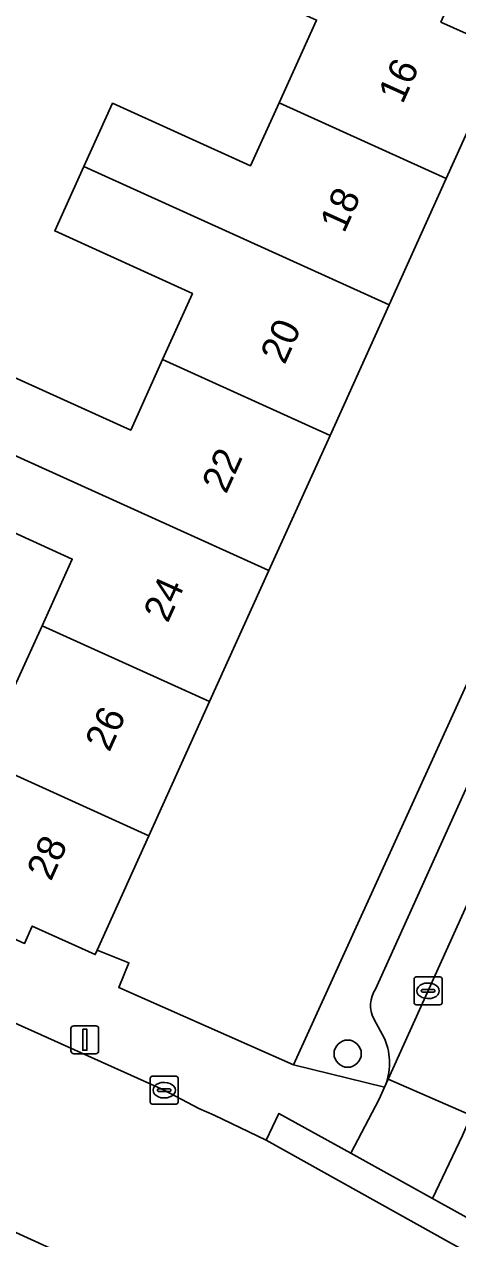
# Model space of a CAD drawing. Extents: x 161838 to 162344, y 381620 to 382160.
# Drawn here: x 162064.83 to 162080.38, y 381747.04 to 381790.62 of the extents above; entities that cross this region are included whole.
import ezdxf

# ---------------------------------------------------------------- set-up
doc = ezdxf.new("R2010")
doc.units = 0
for name, color, linetype in [('IMGEO_Boom', 7, 'Continuous'), ('IMGEO_Erf', 7, 'Continuous'), ('IMGEO_Kolk', 7, 'Continuous'), ('IMGEO_Lichtmast', 7, 'Continuous'), ('IMGEO_Pand', 7, 'Continuous'), ('IMGEO_Pand_nummerreeks', 7, 'Continuous'), ('IMGEO_Parkeervlak_open', 7, 'Continuous'), ('IMGEO_Rijbaan_lokaal_open', 7, 'Continuous'), ('IMGEO_Voetpad_open', 7, 'Continuous')]:
    doc.layers.add(name, color=color, linetype=linetype)

msp = doc.modelspace()

# ---------------------------------------------------------------- linework, layer by layer
at = {"layer": 'IMGEO_Boom'}
msp.add_circle((162076.43, 381753.682), 0.489, dxfattribs=at)
at = {"layer": 'IMGEO_Erf'}
for points in [[(162063.703, 381778.29), (162068.645, 381776.051), (162069.789, 381778.584), (162070.858, 381780.953), (162065.92, 381783.202), (162066.965, 381785.512), (162067.993, 381787.785), (162072.946, 381785.539), (162073.969, 381787.795), (162075.316, 381790.766), (162070.431, 381792.976), (162071.424, 381795.171), (162065.308, 381798.05), (162064.526, 381796.39), (162066.838, 381795.353), (162065.298, 381791.922), (162062.882, 381793.006)], [(162064.418, 381766.726), (162065.465, 381769.039), (162066.546, 381771.429), (162061.613, 381773.671)]]:
    msp.add_lwpolyline(points, dxfattribs=at)
msp.add_lwpolyline([(162068.579, 381756.936), (162068.219, 381756.057), (162074.49, 381753.282), (162089.747, 381786.804), (162083.445, 381789.649), (162083.105, 381788.89), (162081.916, 381789.39), (162079.965, 381785.079), (162077.918, 381780.552), (162075.797, 381775.863), (162073.603, 381771.013), (162071.478, 381766.316), (162069.301, 381761.504), (162067.446, 381757.401)], close=True, dxfattribs=at)
at = {"layer": 'IMGEO_Kolk'}
for p, q in [((162078.813, 381755.511), (162078.813, 381756.363)), ((162078.888, 381756.437), (162079.74, 381756.437)), ((162079.301, 381756.217), (162079.326, 381756.217)), ((162079.814, 381756.363), (162079.814, 381755.511)), ((162079.072, 381755.931), (162079.072, 381755.943)), ((162079.51, 381755.894), (162079.112, 381755.894)), ((162079.115, 381755.98), (162079.513, 381755.98)), ((162079.324, 381755.657), (162079.299, 381755.657)), ((162079.556, 381755.943), (162079.556, 381755.931)), ((162079.74, 381755.437), (162078.888, 381755.437)), ((162069.346, 381751.946), (162069.346, 381752.798)), ((162069.421, 381752.872), (162070.273, 381752.872)), ((162069.834, 381752.652), (162069.859, 381752.652)), ((162070.347, 381752.798), (162070.347, 381751.946)), ((162069.605, 381752.366), (162069.605, 381752.378)), ((162070.043, 381752.329), (162069.645, 381752.329)), ((162069.648, 381752.415), (162070.046, 381752.415)), ((162070.089, 381752.378), (162070.089, 381752.366)), ((162070.273, 381751.872), (162069.421, 381751.872)), ((162069.857, 381752.092), (162069.832, 381752.092))]:
    msp.add_line(p, q, dxfattribs=at)
for points in [[(162078.813, 381755.511), (162078.813, 381756.363)], [(162078.888, 381756.437), (162079.74, 381756.437)], [(162079.814, 381756.363), (162079.814, 381755.511)], [(162079.74, 381755.437), (162078.888, 381755.437)], [(162069.346, 381751.946), (162069.346, 381752.798)], [(162069.421, 381752.872), (162070.273, 381752.872)], [(162070.347, 381752.798), (162070.347, 381751.946)], [(162070.273, 381751.872), (162069.421, 381751.872)]]:
    msp.add_lwpolyline(points, dxfattribs=at)
for centre, radius, start, end in [((162078.89, 381756.361), 0.0765, 91.552, 178.448), ((162078.89, 381756.361), 0.0765, 91.552, 178.448), ((162079.738, 381756.361), 0.0765, 1.552, 88.448), ((162079.738, 381756.361), 0.0765, 1.552, 88.448), ((162079.112, 381755.94), 0.0403, 85.8775, 175.7526), ((162079.109, 381755.93), 0.0366, 178.938, 274.7102), ((162079.513, 381755.937), 0.043, 264.8664, 352.4533), ((162079.517, 381755.942), 0.0386, 1.7309, 96.639), ((162078.89, 381755.513), 0.0765, 181.552, 268.448), ((162078.89, 381755.513), 0.0765, 181.552, 268.448), ((162079.738, 381755.513), 0.0765, 271.552, 358.448), ((162079.738, 381755.513), 0.0765, 271.552, 358.448), ((162069.423, 381752.796), 0.0765, 91.552, 178.448), ((162069.423, 381752.796), 0.0765, 91.552, 178.448), ((162070.271, 381752.796), 0.0765, 1.552, 88.448), ((162070.271, 381752.796), 0.0765, 1.552, 88.448), ((162069.645, 381752.375), 0.0403, 85.8775, 175.7526), ((162069.642, 381752.365), 0.0366, 178.938, 274.7102), ((162070.046, 381752.372), 0.043, 264.8664, 352.4533), ((162070.05, 381752.377), 0.0386, 1.7309, 96.639), ((162069.423, 381751.948), 0.0765, 181.552, 268.448), ((162069.423, 381751.948), 0.0765, 181.552, 268.448), ((162070.271, 381751.948), 0.0765, 271.552, 358.448), ((162070.271, 381751.948), 0.0765, 271.552, 358.448)]:
    msp.add_arc(centre, radius, start, end, dxfattribs=at)
for centre, major_axis, ratio, start_param, end_param in [((162079.3, 381755.937), (-0.387, 0.002), 0.722429, 4.712389, 7.853982), ((162079.325, 381755.937), (-0.39, 0.002), 0.717154, 1.570796, 4.712389), ((162069.833, 381752.372), (-0.387, 0.002), 0.722429, 4.712389, 7.853982), ((162069.858, 381752.372), (-0.39, 0.002), 0.717154, 1.570796, 4.712389)]:
    msp.add_ellipse(centre, major_axis=major_axis, ratio=ratio, start_param=start_param, end_param=end_param, dxfattribs=at)
at = {"layer": 'IMGEO_Lichtmast'}
for p, q in [((162066.503, 381753.781), (162066.503, 381754.581)), ((162066.503, 381754.581), (162066.503, 381753.781)), ((162066.603, 381754.681), (162067.393, 381754.681)), ((162067.393, 381754.681), (162066.603, 381754.681)), ((162067.493, 381754.581), (162067.493, 381753.781)), ((162067.493, 381753.781), (162067.493, 381754.581)), ((162067.393, 381753.681), (162066.603, 381753.681)), ((162066.603, 381753.681), (162067.393, 381753.681))]:
    msp.add_line(p, q, dxfattribs=at)
msp.add_lwpolyline([(162066.923, 381754.556), (162067.073, 381754.556), (162067.073, 381753.806), (162066.923, 381753.806), (162066.923, 381754.556)], dxfattribs=at)
for centre, start, end in [((162066.603, 381754.581), 90, 180), ((162066.603, 381754.581), 90, 180), ((162067.393, 381754.581), 0, 90), ((162067.393, 381754.581), 360, 90), ((162066.603, 381753.781), 180, 270), ((162066.603, 381753.781), 180, 270), ((162067.393, 381753.781), 270, 0), ((162067.393, 381753.781), 270, 0)]:
    msp.add_arc(centre, 0.1, start, end, dxfattribs=at)
at = {"layer": 'IMGEO_Pand'}
for points in [[(162073.969, 381787.795), (162079.965, 381785.079), (162081.916, 381789.39), (162082.043, 381789.672), (162079.775, 381790.698), (162080.088, 381791.39), (162071.424, 381795.171), (162070.431, 381792.976), (162075.316, 381790.766)], [(162077.918, 381780.552), (162079.965, 381785.079), (162073.969, 381787.795), (162072.946, 381785.539), (162067.993, 381787.785), (162066.965, 381785.512)], [(162075.797, 381775.863), (162077.918, 381780.552), (162066.965, 381785.512), (162065.92, 381783.202), (162070.858, 381780.953), (162069.789, 381778.584)], [(162075.797, 381775.863), (162069.789, 381778.584), (162068.645, 381776.051), (162063.703, 381778.29), (162062.654, 381775.972), (162073.603, 381771.013)], [(162065.465, 381769.039), (162071.478, 381766.316), (162073.603, 381771.013), (162062.654, 381775.972), (162061.613, 381773.671), (162066.546, 381771.429)], [(162069.301, 381761.504), (162071.478, 381766.316), (162065.465, 381769.039), (162064.418, 381766.726), (162059.499, 381768.952), (162058.368, 381766.456)], [(162069.301, 381761.504), (162058.368, 381766.456), (162057.435, 381764.397), (162062.381, 381762.156), (162061.101, 381759.332), (162064.835, 381757.639), (162065.115, 381758.257), (162067.371, 381757.236), (162067.446, 381757.401)]]:
    msp.add_lwpolyline(points, close=True, dxfattribs=at)
at = {"layer": 'IMGEO_Parkeervlak_open'}
for points in [[(162077.753, 381752.48), (162077.885, 381752.773), (162091.2, 381782.254)], [(162088.368, 381780.23), (162077.427, 381756)], [(162077.369, 381754.933), (162077.765, 381754.199)]]:
    msp.add_lwpolyline(points, dxfattribs=at)
for centre, radius, start, end in [((162078.307, 381755.417), 1.056, 146.4825, 207.2947), ((162075.671, 381753.354), 2.258, 337.2236, 21.9765)]:
    msp.add_arc(centre, radius, start, end, dxfattribs=at)
at = {"layer": 'IMGEO_Rijbaan_lokaal_open'}
for points in [[(162094.929, 381782.528), (162095.383, 381783.532), (162092.357, 381784.815), (162091.2, 381782.254), (162077.885, 381752.773), (162080.868, 381751.463)], [(162080.79, 381751.291), (162080.868, 381751.463), (162077.885, 381752.773), (162077.753, 381752.48), (162077.557, 381752.046), (162076.538, 381750.111), (162079.471, 381748.488), (162080.545, 381750.749)]]:
    msp.add_lwpolyline(points, close=True, dxfattribs=at)
msp.add_lwpolyline([(162015.372, 381769.412), (162017.318, 381768.637), (162049.197, 381754.238), (162052.77, 381752.631), (162056.86, 381750.762), (162068.214, 381745.584), (162068.985, 381745.23), (162081.324, 381741.038), (162082.15, 381740.62), (162087.294, 381738.315), (162101.774, 381731.795), (162101.956, 381731.713), (162103.87, 381735.811), (162103.292, 381736.059), (162084.495, 381744.526), (162081.506, 381746.115), (162073.51, 381750.574), (162071.642, 381751.481), (162071.089, 381751.71), (162069.847, 381752.372), (162047.793, 381762.29), (162043.964, 381764.024), (162019.542, 381775.175)], dxfattribs=at)
at = {"layer": 'IMGEO_Voetpad_open'}
for points in [[(162064.04, 381798.645), (162065.308, 381798.05), (162071.424, 381795.171), (162080.088, 381791.39), (162079.775, 381790.698), (162082.043, 381789.672), (162081.916, 381789.39), (162083.105, 381788.89), (162083.445, 381789.649), (162089.747, 381786.804), (162092.357, 381784.815), (162095.383, 381783.532), (162098.526, 381782.429), (162100.887, 381781.363), (162101.163, 381781.976), (162104.902, 381780.293), (162119.551, 381773.591)], [(162092.357, 381784.815), (162089.747, 381786.804), (162074.49, 381753.282), (162077.753, 381752.48)], [(162074.49, 381753.282), (162068.219, 381756.057), (162068.579, 381756.936), (162067.446, 381757.401), (162067.371, 381757.236), (162065.115, 381758.257), (162064.835, 381757.639), (162061.101, 381759.332), (162056.054, 381761.616), (162050.052, 381764.333), (162049.942, 381764.37), (162048.674, 381764.793), (162048.513, 381764.865), (162045.047, 381766.421), (162038.572, 381769.363), (162032.236, 381772.242), (162025.763, 381775.183), (162026.727, 381777.305), (162025.108, 381777.668), (162022.125, 381778.338), (162018.222, 381779.214), (162009.992, 381781.058), (162007.821, 381781.474), (162004.221, 381782.086)], [(162077.427, 381756), (162088.368, 381780.23)], [(162019.542, 381775.175), (162043.964, 381764.024), (162044.441, 381765.033), (162048.229, 381763.319), (162047.793, 381762.29), (162069.847, 381752.372), (162071.089, 381751.71), (162071.642, 381751.481), (162073.51, 381750.574), (162073.964, 381751.536), (162076.538, 381750.111), (162077.557, 381752.046), (162077.753, 381752.48), (162074.49, 381753.282)], [(162068.985, 381745.23), (162068.214, 381745.584), (162056.86, 381750.762), (162052.77, 381752.631), (162052.283, 381751.622), (162048.804, 381753.263), (162049.197, 381754.238), (162017.318, 381768.637), (162015.372, 381769.412), (162014.939, 381768.441)], [(162077.765, 381754.199), (162077.369, 381754.933)], [(162115.037, 381735.042), (162110.328, 381737.182), (162109.441, 381737.584), (162109.199, 381737.693), (162094.462, 381744.361), (162085.784, 381748.23), (162086.038, 381748.793), (162083.788, 381749.81), (162080.79, 381751.291), (162080.545, 381750.749), (162079.471, 381748.488), (162082.026, 381747.073), (162081.506, 381746.115), (162084.495, 381744.526)]]:
    msp.add_lwpolyline(points, dxfattribs=at)
msp.add_lwpolyline([(162073.964, 381751.536), (162073.51, 381750.574), (162081.506, 381746.115), (162082.026, 381747.073), (162079.471, 381748.488), (162076.538, 381750.111)], close=True, dxfattribs=at)
for centre, radius, start, end in [((162078.307, 381755.417), 1.056, 146.4825, 207.2947), ((162075.671, 381753.354), 2.258, 337.2236, 21.9765)]:
    msp.add_arc(centre, radius, start, end, dxfattribs=at)

# ---------------------------------------------------------------- texts
at = {"layer": 'IMGEO_Pand_nummerreeks'}
for s, p in [('16', (162078.397, 381787.724)), ('18', (162076.302, 381783.093)), ('20', (162074.168, 381778.376)), ('22', (162072.07, 381773.737)), ('24', (162069.975, 381769.106)), ('26', (162067.879, 381764.473)), ('28', (162065.784, 381759.841))]:
    msp.add_text(s, height=1, rotation=65.661, dxfattribs=at).set_placement(p)

doc.saveas('drawing.dxf')
